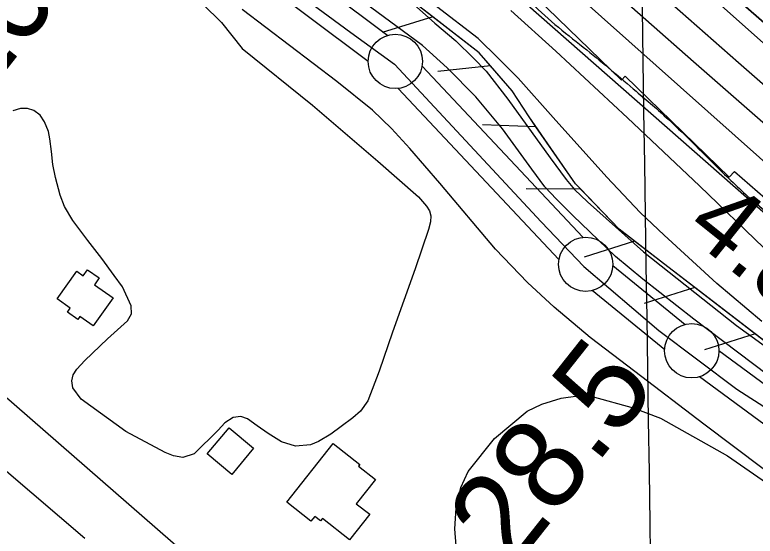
# Model space of a CAD drawing. Extents: x 3823584 to 3861785, y 301729 to 327625.
# Drawn here: x 3837614 to 3838296, y 323402 to 323882 of the extents above; entities that cross this region are included whole.
import ezdxf

# ---------------------------------------------------------------- set-up
doc = ezdxf.new("R2010")
doc.units = 0
for name, color, linetype in [('V-BLDG-OTLN', 7, 'Continuous'), ('V-FLOD-BASE', 7, 'Continuous'), ('V-GRID-MAJR', 7, 'Continuous'), ('V-LEVE-TOET', 7, 'Continuous'), ('V-RIVR-EDGE', 7, 'Continuous'), ('V-RIVR-RANG', 7, 'Continuous'), ('V-RIVR-RANG-IDEN', 7, 'Continuous'), ('V-ROAD-CNTR', 7, 'Continuous'), ('V-RRAP-FSHR', 7, 'Continuous'), ('V-RRAP-RVMT', 7, 'Continuous'), ('V-SITE-VEGE', 7, 'Continuous'), ('V-SURV-LINE', 7, 'Continuous'), ('V-TOPO-DPTH', 7, 'Continuous'), ('V-TOPO-MINR', 7, 'Continuous'), ('V-TOPO-WATR', 7, 'Continuous')]:
    doc.layers.add(name, color=color, linetype=linetype)

msp = doc.modelspace()

# ---------------------------------------------------------------- linework, layer by layer
at = {"layer": 'V-BLDG-OTLN'}
for points in [[(3837704.382, 323620.898), (3837686.186, 323595.218), (3837673.8850000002, 323603.934), (3837671.897, 323601.128), (3837662.404, 323607.856), (3837664.931, 323611.42100000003), (3837652.912, 323619.93700000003), (3837671.041, 323645.525), (3837676.992, 323641.306), (3837680.943, 323646.881), (3837691.6520000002, 323639.293), (3837687.23, 323633.05)], [(3837813.7290000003, 323458.43200000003), (3837791.094, 323477.337), (3837811.208, 323501.417), (3837833.84, 323482.512)], [(3837922.269, 323398.243), (3837897.261, 323417.955), (3837895.333, 323415.51), (3837890.082, 323419.647), (3837886.6520000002, 323415.295), (3837864.531, 323432.729), (3837907.109, 323486.749), (3837931.585, 323467.455), (3837930.487, 323466.063), (3837945.978, 323453.855), (3837928.308, 323431.43700000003), (3837940.721, 323421.654)]]:
    msp.add_lwpolyline(points, close=True, dxfattribs=at)
at = {"layer": 'V-FLOD-BASE'}
for points in [[(3837614.6040000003, 324124.417), (3837627.363, 324120.974), (3837647.0300000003, 324069.67), (3837741.944, 324004.683), (3837760.755, 323987.582), (3837818.9, 323947.392), (3837841.133, 323926.015), (3837923.219, 323865.306), (3837963.409, 323836.232), (3838098.511, 323690.87), (3838137.845, 323649.826), (3838207.1070000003, 323590.825), (3838278.932, 323536.956), (3838308.005, 323518.143)], [(3838540.65, 323375.59), (3838440.128, 323450.043), (3838334.771, 323529.086), (3838239.1950000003, 323601.329), (3838192.201, 323638.091), (3838167.136, 323659.156), (3838127.884, 323696.866), (3838112.796, 323711.925), (3838102.052, 323723.193), (3838089.949, 323739.526), (3838062.8910000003, 323776.568), (3838038.3680000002, 323806.162), (3838012.1410000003, 323832.689), (3837989.255, 323853.44800000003), (3837958.84, 323875.835), (3837915.983, 323907.51300000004), (3837868.285, 323941.999), (3837806.671, 323988.462), (3837738.9280000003, 324037.739), (3837671.686, 324088.401)]]:
    msp.add_lwpolyline(points, dxfattribs=at)
at = {"layer": 'V-GRID-MAJR'}
msp.add_spline([(3838444.8910000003, 307319.343), (3838352.38, 313376.366), (3838259.823, 319436.473), (3838167.2660000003, 325496.576), (3838167.219, 325499.664)], degree=3, dxfattribs=at)
at = {"layer": 'V-LEVE-TOET'}
for points in [[(3838383.812, 323402.648), (3838248.343, 323504.672), (3838184.759, 323553.031), (3838143.8850000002, 323584.601), (3838110.623, 323612.259), (3838086.062, 323635.01), (3838056.589, 323665.72000000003), (3838005.272, 323726.605), (3837977.788, 323758.396), (3837960.937, 323777.03500000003), (3837943.382, 323793.89400000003), (3837910.413, 323820.262), (3837823.328, 323886.607)], [(3837983.69, 323888.862), (3838000.66, 323873.989), (3838019.9050000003, 323857.616), (3838036.275, 323841.756), (3838047.907, 323829.591), (3838067.99, 323803.991), (3838106.949, 323750.02), (3838121.7090000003, 323729.806), (3838129.3910000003, 323720.738), (3838141.327, 323709.365), (3838192.728, 323663.256), (3838278.414, 323595.531), (3838359.394, 323536.76)]]:
    msp.add_lwpolyline(points, dxfattribs=at)
at = {"layer": 'V-RIVR-EDGE'}
msp.add_spline([(3836304.3756208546, 325474.18490968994), (3836346.414637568, 325438.3248399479), (3836389.407230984, 325406.0749957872), (3836417.6425015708, 325385.4333151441), (3836442.6682071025, 325366.7281829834), (3836470.247893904, 325340.94515767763), (3836497.8244014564, 325313.8763988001), (3836554.9028376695, 325258.4483785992), (3836598.5128638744, 325215.91107623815), (3836636.356164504, 325181.10248193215), (3836681.25510353, 325139.84773389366), (3836737.070060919, 325093.42302794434), (3836790.9421113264, 325041.2172897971), (3836840.3252216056, 324993.52274652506), (3836889.068644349, 324947.1155264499), (3836934.613629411, 324907.1449223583), (3836980.8110190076, 324871.0299293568), (3837015.471778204, 324849.0866188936), (3837040.494304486, 324829.09575316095), (3837085.3916538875, 324787.1981383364), (3837143.7621821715, 324734.3384060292), (3837181.60866205, 324700.815545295), (3837223.2932671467, 324659.5687453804), (3837272.052586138, 324619.5901931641), (3837314.3832372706, 324579.6275371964), (3837346.4455057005, 324546.7618498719), (3837364.398086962, 324527.4313367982), (3837395.83179523, 324500.35304017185), (3837442.024415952, 324462.30944681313), (3837492.7139249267, 324422.9689925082), (3837554.3051456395, 324372.67277922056), (3837573.562535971, 324361.05348832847), (3837583.2007688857, 324359.1010435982), (3837596.685075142, 324352.6389936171), (3837621.0774516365, 324337.7926517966), (3837648.0333471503, 324319.7256175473), (3837677.5368654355, 324292.00922300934), (3837718.5754244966, 324249.4782791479), (3837753.847257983, 324214.6760433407), (3837781.426944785, 324188.89301803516), (3837800.047826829, 324179.8467839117), (3837819.9544424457, 324170.79737053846), (3837850.7214395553, 324134.0776617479), (3837874.448694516, 324110.2327745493), (3837909.0728923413, 324073.5035280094), (3837941.7780275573, 324040.63625106), (3837989.872225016, 323991.65915346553), (3838022.5821291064, 323960.7204768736), (3838034.1219387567, 323947.83452790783), (3838046.301435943, 323933.66125574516), (3838066.8302532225, 323916.25298453), (3838089.9146413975, 323892.40968695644), (3838140.5946126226, 323849.2120319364), (3838186.144366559, 323811.1700282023), (3838215.652653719, 323785.38223402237), (3838265.675451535, 323736.40036755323), (3838297.1043909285, 323707.3934705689), (3838336.8747022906, 323671.9372406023), (3838359.952731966, 323645.5224758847), (3838385.6228939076, 323627.4586208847), (3838404.2374174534, 323615.8409196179), (3838421.5598489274, 323601.65493045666), (3838441.441030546, 323582.31964850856), (3838460.0476059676, 323567.48761331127), (3838468.395336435, 323563.60974747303), (3838484.446340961, 323555.21273863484), (3838548.5883636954, 323496.55289863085), (3838595.4381578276, 323464.2935167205), (3838649.9785090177, 323422.37205752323), (3838701.302936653, 323379.8156796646), (3838749.433695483, 323345.62451814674), (3838798.2232173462, 323317.86043486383), (3838856.617590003, 323274.6437043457), (3838932.9883882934, 323221.7394625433), (3838989.4684672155, 323184.31330197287), (3839037.599226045, 323150.12214045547), (3839068.4186807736, 323134.6170356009), (3839093.417362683, 323104.98316807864), (3839110.730256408, 323086.93997820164), (3839122.930418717, 323081.1239742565), (3839143.464004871, 323065.6443033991), (3839172.3405526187, 323044.35816634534), (3839190.955076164, 323032.7404650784), (3839215.98555057, 323015.9639332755), (3839242.319244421, 323006.25575686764), (3839316.801182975, 322969.42795358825), (3839341.8396055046, 322955.86575571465), (3839371.3828644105, 322944.2210308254), (3839391.2910696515, 322935.81448423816), (3839417.6104568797, 322920.32050675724), (3839461.26181333, 322894.4977408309), (3839483.709693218, 322873.22750002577), (3839520.2990527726, 322851.27942068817), (3839555.6010891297, 322828.6916538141), (3839599.9048501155, 322806.7244989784), (3839718.698497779, 322751.1438747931), (3839768.138834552, 322726.5925358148), (3839807.9457072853, 322705.9222419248), (3839836.8508682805, 322696.20770701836), (3839865.0988558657, 322680.7089606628), (3839887.567400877, 322667.7959880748), (3839924.172656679, 322652.2765765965), (3839969.7621512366, 322630.306242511), (3840004.4324481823, 322612.2201327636), (3840037.8249596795, 322597.35153619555), (3840085.3541819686, 322579.87650073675), (3840108.4624145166, 322565.6762049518), (3840121.9212867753, 322548.928286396), (3840123.184765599, 322539.92497214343), (3840122.5260025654, 322533.4978939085), (3840117.9957321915, 322521.29455234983), (3840112.8353120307, 322514.2357347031), (3840095.465191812, 322509.1357202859), (3840089.6793907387, 322509.1500269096), (3840085.168195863, 322504.661086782), (3840084.5094328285, 322498.2340085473), (3840085.779270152, 322491.8021614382), (3840130.719539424, 322467.2619498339), (3840169.888314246, 322448.52184592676), (3840197.5093312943, 322439.45335705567), (3840209.076164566, 322437.4961434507), (3840231.586039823, 322441.2977072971), (3840246.3910513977, 322448.9755473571), (3840266.343766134, 322458.5692707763), (3840273.434376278, 322466.26618633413), (3840278.590027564, 322471.3964036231), (3840288.898150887, 322480.37110462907), (3840295.9808129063, 322484.8536862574), (3840301.7666139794, 322484.8393796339), (3840308.195281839, 322484.8234833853), (3840320.395444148, 322479.00747944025), (3840324.873256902, 322469.99621706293), (3840326.781192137, 322461.6341799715), (3840338.324181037, 322450.0339645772), (3840344.7401318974, 322444.87513404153), (3840366.580116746, 322437.7495521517), (3840385.842275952, 322428.05886161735), (3840421.7967168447, 322409.3267058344), (3840466.0957089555, 322385.43095064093), (3840492.411916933, 322368.65123958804), (3840506.526372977, 322357.0446656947), (3840533.4854477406, 322340.2633650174), (3840559.1778644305, 322331.1996450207), (3840587.441748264, 322322.12956652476), (3840611.8452521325, 322311.78329220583), (3840642.0218400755, 322296.27977697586), (3840678.615968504, 322276.2602979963), (3840712.637040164, 322255.60431073), (3840733.1753951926, 322242.05324023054), (3840784.5268464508, 322210.42559773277), (3840835.889425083, 322183.29802273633), (3840892.388579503, 322153.5862635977), (3840923.854080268, 322139.3653026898), (3840950.8242824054, 322127.08406951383), (3840989.3295253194, 322099.98828701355), (3841017.5727440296, 322082.56094030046), (3841061.238407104, 322062.5239754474), (3841092.6943701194, 322044.4458138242), (3841151.0982805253, 322005.0862840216), (3841210.7847452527, 321964.43784139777), (3841240.294622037, 321939.29291400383), (3841299.971549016, 321894.78727066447), (3841335.8926077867, 321862.55491237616), (3841374.3692374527, 321823.88752772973), (3841411.5712609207, 321789.72338983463), (3841444.922442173, 321758.1402568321), (3841469.94019958, 321736.22079074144), (3841482.124465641, 321723.9761189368), (3841496.2198461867, 321704.6551436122), (3841509.051747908, 321694.3374825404), (3841523.1773313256, 321687.23097614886), (3841573.8986327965, 321660.747857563), (3841623.970708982, 321631.69486145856), (3841667.623655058, 321606.5149623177), (3841696.5208679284, 321593.58609348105), (3841738.2626995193, 321575.48249786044), (3841787.074476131, 321556.7185495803), (3841815.992354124, 321552.1469489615), (3841851.3325414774, 321544.9879849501), (3841886.661601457, 321533.32895343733), (3841930.322495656, 321511.36338822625), (3841950.219573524, 321498.4567741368), (3841977.1818275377, 321482.9612070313), (3841998.380535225, 321476.4800815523), (3842052.9924195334, 321463.4876277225), (3842082.546805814, 321456.3429703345), (3842109.5185975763, 321444.7046039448), (3842146.1190845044, 321427.2565921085), (3842196.2006984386, 321402.06079671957), (3842241.1346092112, 321374.94911797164), (3842288.6336286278, 321345.2596135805), (3842321.375325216, 321327.17827270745), (3842366.940975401, 321295.56493683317), (3842395.188962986, 321280.06619047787), (3842429.2227516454, 321264.5531374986), (3842452.3516493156, 321258.7101099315), (3842470.9725313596, 321249.663875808)], degree=3, dxfattribs=at)
at = {"layer": 'V-ROAD-CNTR'}
msp.add_lwpolyline([(3835362.231236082, 325460.9250527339), (3835509.512941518, 325334.346305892), (3835871.754217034, 325022.76592905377), (3836108.39574375, 324817.59833938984), (3836413.993132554, 324556.9258607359), (3836839.7512810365, 324193.6555872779), (3837163.6936331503, 323918.79213700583), (3837445.019070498, 323669.35663587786), (3837836.483287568, 323328.41131777), (3838069.5748213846, 323134.8777048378), (3838125.3817097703, 323086.7958010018), (3838255.977448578, 322989.4639956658), (3838600.004760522, 322735.3525038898), (3839019.3109219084, 322425.41512376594), (3839565.53882945, 322022.9139287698), (3840024.8789107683, 321675.2296241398), (3840474.8730107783, 321349.99327461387), (3840728.35650381, 321161.30865198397)], dxfattribs=at)
at = {"layer": 'V-RRAP-FSHR'}
for p, q in [((3837998.901, 323879.704), (3837952.2320000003, 323865.338)), ((3838052.042, 323834.491), (3838003.489, 323829.29)), ((3838093.46, 323778.288), (3838044.667, 323780.19800000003)), ((3838133.739, 323721.028), (3838084.9080000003, 323721.19800000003)), ((3838184.6920000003, 323673.09500000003), (3838138.129, 323658.386)), ((3838240.214, 323630.468), (3838193.629, 323615.83)), ((3838295.7060000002, 323587.8), (3838249.1210000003, 323573.162))]:
    msp.add_line(p, q, dxfattribs=at)
for points in [[(3836295.022645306, 325470.7968986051), (3836414.504487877, 325364.55863442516), (3836757.995048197, 325057.7969061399), (3837184.2616725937, 324676.31799378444), (3837417.6558488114, 324483.21002560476), (3837615.799848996, 324305.9576734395), (3837777.405481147, 324176.4257693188), (3837917.933097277, 324038.7141531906), (3838584.546857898, 323453.1786646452)], [(3838516.713, 323417.868), (3838211.373, 323652.64400000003), (3838170.335, 323684.099), (3838130.324, 323725.941), (3838087.472, 323787.59500000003), (3838072.042, 323811.577), (3838041.543, 323846.521), (3837978.9390000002, 323895.239), (3837748.075, 324066.564), (3837693.8540000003, 324106.458), (3837694.89, 324135.743), (3837697.0100000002, 324164.456), (3837695.298, 324176.805), (3837684.201, 324193.14400000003), (3837666.4820000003, 324209.091), (3837608.497, 324250.814), (3837483.473, 324345.729), (3837295.8910000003, 324482.542), (3837082.919, 324641.37), (3836929.9, 324758.229), (3836898.7800000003, 324781.855)], [(3837998.901, 323879.704), (3837978.9390000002, 323895.239), (3837943.039, 323921.88)], [(3838052.042, 323834.491), (3838041.543, 323846.521), (3837998.901, 323879.705)], [(3838093.788, 323778.507), (3838087.472, 323787.59500000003), (3838072.042, 323811.577), (3838052.042, 323834.492)], [(3838134.4590000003, 323721.617), (3838130.324, 323725.941), (3838093.788, 323778.50800000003)], [(3838184.6920000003, 323673.09500000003), (3838170.335, 323684.099), (3838134.458, 323721.618)], [(3838295.7060000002, 323587.8), (3838240.214, 323630.468), (3838211.373, 323652.64400000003), (3838184.691, 323673.09500000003)], [(3838351.198, 323545.13300000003), (3838295.705, 323587.801)]]:
    msp.add_lwpolyline(points, dxfattribs=at)
at = {"layer": 'V-RRAP-RVMT'}
for p, q in [((3838082.037000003, 323909.61800000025), (3838172.7520000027, 323821.48400000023)), ((3838172.7520000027, 323821.48400000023), (3838176.1280000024, 323825.0290000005)), ((3838176.128000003, 323825.0290000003), (3838271.7100000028, 323732.11700000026)), ((3838271.7100000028, 323732.11700000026), (3838276.6870000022, 323737.31000000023)), ((3838276.6870000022, 323737.31000000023), (3838377.613000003, 323648.953))]:
    msp.add_line(p, q, dxfattribs=at)
at = {"layer": 'V-SITE-VEGE'}
for points in [[(3838301.954, 323599.185), (3838260.5, 323634.13), (3838211.87, 323678.731), (3838189.778, 323699.684), (3838159.1240000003, 323732.09), (3838109.657, 323786.913), (3838077.437, 323823.093), (3838059.098, 323841.641), (3838040.559, 323859.69800000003), (3838002.352, 323889.37), (3837949.224, 323928.24700000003), (3837926.424, 323947.22000000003), (3837914.802, 323960.673), (3837909.188, 323967.647), (3837898.545, 323979.212), (3837886.603, 323989.097), (3837874.853, 323998.188), (3837862.309, 324006.987), (3837849.686, 324018.957), (3837842.792, 324027.229), (3837823.469, 324047.072), (3837811.2260000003, 324056.266)], [(3837769.846, 323908.697), (3837804.353, 323874.592), (3837823.35, 323850.489)], [(3838070.6550000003, 323885.507), (3838112.09, 323848.183), (3838177.98, 323786.72000000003), (3838244.556, 323724.064), (3838303.631, 323667.002)], [(3837823.35, 323850.489), (3837888.194, 323798.45900000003), (3837948.082, 323746.759), (3837985.769, 323714.12), (3837993.056, 323705.255), (3837995.808, 323701.075), (3837997.0700000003, 323696.407), (3837996.642, 323690.958), (3837994.8170000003, 323683.829), (3837982.5130000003, 323647.71), (3837961.855, 323589.43), (3837949.454, 323553.412), (3837939.085, 323526.204), (3837932.29, 323516.724), (3837925.312, 323510.619), (3837914.46, 323502.449), (3837904.8030000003, 323495.466), (3837893.558, 323488.689), (3837886.203, 323485.558), (3837872.318, 323484.349), (3837859.649, 323488.48600000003), (3837847.199, 323496.092), (3837837.2260000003, 323502.992), (3837828.241, 323509.587), (3837822.105, 323511.803), (3837814.861, 323510.656), (3837807.3000000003, 323506.038), (3837801.113, 323499.03500000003), (3837779.177, 323477.347), (3837768.747, 323474.03500000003), (3837760.028, 323475.375), (3837752.412, 323478.492), (3837716.1350000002, 323497.835), (3837675.061, 323527.615), (3837667.389, 323538.26900000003), (3837666.531, 323544.51900000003), (3837667.754, 323550.065), (3837670.955, 323555.204), (3837678.239, 323563.291), (3837699.373, 323583.298), (3837717.7120000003, 323599.949), (3837721.319, 323606.373), (3837721.159, 323613.512), (3837713.129, 323631.009), (3837705.259, 323641.564), (3837693.9450000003, 323657.096), (3837681.1520000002, 323673.627), (3837667.475, 323692.147), (3837659.815, 323705.181), (3837655.613, 323715.515), (3837651.245, 323731.89900000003), (3837648.932, 323743.81), (3837647.613, 323755.715), (3837646.094, 323767.426), (3837644.845, 323774.272), (3837641.2260000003, 323782.92100000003), (3837637.294, 323789.09), (3837631.469, 323793.485), (3837625.5300000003, 323795.205), (3837619.185, 323795.24), (3837611.935, 323793.102)], [(3837181.573, 323388.368), (3837235.806, 323443.369), (3837288.271, 323500.754), (3837323.0100000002, 323543.571), (3837334.6010000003, 323560.06), (3837339.41, 323568.755), (3837343.438, 323580.03), (3837344.782, 323589.438), (3837343.852, 323600.248), (3837338.026, 323621.393), (3837336.223, 323635.477), (3837337.473, 323645.783), (3837342.39, 323656.357), (3837348.065, 323660.983), (3837352.433, 323662.146), (3837356.988, 323661.427), (3837361.4420000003, 323660.215), (3837388.785, 323640.53), (3837439.117, 323602.38), (3837516.558, 323538.201), (3837606.316, 323461.369), (3837678.3170000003, 323399.703)], [(3838022.166, 323369.272), (3838019.018, 323408.256), (3838020.3170000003, 323427.284), (3838024.6890000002, 323446.396), (3838031.417, 323461.031), (3838055.684, 323491.53), (3838085.771, 323516.63800000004), (3838099.191, 323523.106), (3838117.169, 323528.457), (3838132.252, 323530.65), (3838145.632, 323530.079), (3838183.251, 323519.651), (3838208.481, 323510.185), (3838270.248, 323475.526), (3838321.997, 323439.637)]]:
    msp.add_lwpolyline(points, dxfattribs=at)
at = {"layer": 'V-SURV-LINE'}
for points in [[(3837677.831647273, 324072.2282276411), (3837957.3420831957, 323862.61222554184)], [(3837939.325520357, 323838.62464664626), (3837659.815136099, 324048.2406100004)], [(3837988.948749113, 323834.3080306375), (3838136.858693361, 323676.7065996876)], [(3838114.9687699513, 323656.1924162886), (3837967.058757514, 323813.7939198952)], [(3838164.54895194, 323650.8873931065), (3838231.325604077, 323596.4712464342)], [(3838212.381452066, 323573.2092776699), (3838145.605106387, 323627.62517461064)], [(3838262.3282462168, 323572.4525766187), (3838967.899995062, 323053.09216806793)], [(3838950.103352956, 323028.9409823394), (3838244.5316223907, 323548.30137743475)]]:
    msp.add_lwpolyline(points, dxfattribs=at)
for centre in [(3837964.3254700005, 323838.6258), (3838139.59206, 323651.87473000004), (3838237.338330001, 323572.2216199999)]:
    msp.add_circle(centre, 25, dxfattribs=at)
at = {"layer": 'V-TOPO-DPTH'}
for points in [[(3838382.7371031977, 323805.5230493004), (3837860.9331754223, 324260.5584050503), (3837832.560879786, 324285.4311535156), (3837804.275892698, 324310.4022774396), (3837776.121868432, 324335.5209645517), (3837748.0551527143, 324360.7380271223), (3837699.881196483, 324404.2489813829), (3837695.951561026, 324407.76680775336), (3837692.0014180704, 324411.2612445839), (3837688.0205138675, 324414.7205971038), (3837684.0191021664, 324418.1565600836), (3837578.9735416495, 324507.55360117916), (3837522.3488812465, 324555.5693497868), (3837465.6107774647, 324603.45018290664), (3837408.7025086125, 324651.1286427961), (3837351.6807963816, 324698.6721871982), (3836968.178114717, 325017.27296973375)], [(3838382.7371031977, 323805.5230493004), (3837860.9331754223, 324260.5584050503), (3837832.560879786, 324285.4311535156), (3837804.275892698, 324310.4022774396), (3837776.121868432, 324335.5209645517), (3837748.0551527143, 324360.7380271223), (3837699.881196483, 324404.2489813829), (3837695.951561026, 324407.76680775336), (3837692.0014180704, 324411.2612445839), (3837688.0205138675, 324414.7205971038), (3837684.0191021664, 324418.1565600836), (3837578.9735416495, 324507.55360117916), (3837522.3488812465, 324555.5693497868), (3837465.6107774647, 324603.45018290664), (3837408.7025086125, 324651.1286427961), (3837351.6807963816, 324698.6721871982), (3836968.178114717, 325017.27296973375)], [(3836971.9178616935, 324972.83050933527), (3837252.283767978, 324737.8850834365), (3837322.0034214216, 324679.353446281), (3837391.652678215, 324620.7383131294), (3837461.196340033, 324561.99793598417), (3837530.6696052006, 324503.1740628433), (3837611.3959127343, 324434.6972930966), (3837640.340531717, 324409.9202919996), (3837669.1349194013, 324384.971469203), (3837697.7039601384, 324359.76491385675), (3837726.122769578, 324334.38653681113), (3838066.8243204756, 324027.3728192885), (3838119.971225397, 323979.69030236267), (3838173.255810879, 323932.1628219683), (3838226.746917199, 323884.8678963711), (3838280.3757040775, 323837.7280073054), (3838339.2406858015, 323786.21231701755)], [(3836971.9178616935, 324972.83050933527), (3837252.283767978, 324737.8850834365), (3837322.0034214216, 324679.353446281), (3837391.652678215, 324620.7383131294), (3837461.196340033, 324561.99793598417), (3837530.6696052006, 324503.1740628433), (3837611.3959127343, 324434.6972930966), (3837640.340531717, 324409.9202919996), (3837669.1349194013, 324384.971469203), (3837697.7039601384, 324359.76491385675), (3837726.122769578, 324334.38653681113), (3838066.8243204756, 324027.3728192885), (3838119.971225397, 323979.69030236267), (3838173.255810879, 323932.1628219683), (3838226.746917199, 323884.8678963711), (3838280.3757040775, 323837.7280073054), (3838339.2406858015, 323786.21231701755)], [(3838324.934771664, 323727.84568335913), (3838008.706183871, 324009.45784384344), (3837946.1737909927, 324065.22076796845), (3837883.691674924, 324121.0398939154), (3837821.284974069, 324176.94332259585), (3837758.928550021, 324232.9029530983), (3837651.055469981, 324329.84148260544), (3837642.64045044, 324337.3363473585), (3837634.181647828, 324344.78101785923), (3837625.657170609, 324352.1503969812), (3837617.0889103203, 324359.46958185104), (3837330.422620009, 324602.1558655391), (3837256.6802777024, 324663.8755040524), (3837182.482062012, 324725.03570046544), (3837107.600036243, 324785.35673372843), (3837032.2621370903, 324845.1183248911)]]:
    msp.add_lwpolyline(points, dxfattribs=at)
at = {"layer": 'V-TOPO-MINR'}
for points in [[(3836968.178114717, 325017.27296973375), (3837351.6807963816, 324698.6721871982), (3837408.7025086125, 324651.1286427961), (3837465.6107774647, 324603.45018290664), (3837522.3488812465, 324555.5693497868), (3837578.9735416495, 324507.55360117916), (3837684.0191021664, 324418.1565600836), (3837688.0205138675, 324414.7205971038), (3837692.0014180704, 324411.2612445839), (3837695.951561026, 324407.76680775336), (3837699.881196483, 324404.2489813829), (3837748.0551527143, 324360.7380271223), (3837776.121868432, 324335.5209645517), (3837804.275892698, 324310.4022774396), (3837832.560879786, 324285.4311535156), (3837860.9331754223, 324260.5584050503), (3838382.7371031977, 323805.5230493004)], [(3836970.0586820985, 324997.1175565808), (3837628.9950841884, 324452.9762194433), (3837638.6086303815, 324445.0056336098), (3837648.201167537, 324437.00994346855), (3837657.7621911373, 324428.97659686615), (3837667.3022057, 324420.91814595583), (3837684.932040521, 324405.96673235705), (3837685.638491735, 324405.3618598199), (3837687.7308906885, 324403.5164530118), (3837696.1927654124, 324395.8702342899), (3837701.1188868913, 324391.4292447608), (3837706.0518067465, 324386.9958371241), (3837710.9949241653, 324382.57380232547), (3837715.944839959, 324378.15934941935), (3838361.295295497, 323803.9532928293)], [(3836971.9178616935, 324972.83050933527), (3837252.283767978, 324737.8850834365), (3837322.0034214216, 324679.353446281), (3837391.652678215, 324620.7383131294), (3837461.196340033, 324561.99793598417), (3837530.6696052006, 324503.1740628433), (3837611.3959127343, 324434.6972930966), (3837640.340531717, 324409.9202919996), (3837669.1349194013, 324384.971469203), (3837697.7039601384, 324359.76491385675), (3837726.122769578, 324334.38653681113), (3838066.8243204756, 324027.3728192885), (3838119.971225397, 323979.69030236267), (3838173.255810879, 323932.1628219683), (3838226.746917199, 323884.8678963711), (3838280.3757040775, 323837.7280073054), (3838339.2406858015, 323786.21231701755)], [(3837123.035889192, 324815.42369030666), (3837165.697822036, 324778.91920664), (3837614.615881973, 324394.3863041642), (3837632.534403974, 324378.9380260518), (3837650.386447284, 324363.4137931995), (3837668.1387725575, 324347.775628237), (3837685.824619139, 324332.06150853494), (3838107.247108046, 323955.20173551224), (3838151.018769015, 323916.2039689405), (3838194.8860438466, 323877.3144568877), (3838238.896739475, 323838.58732661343), (3838283.0030489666, 323799.96845085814), (3838362.0912485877, 323730.97767757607)]]:
    msp.add_lwpolyline(points, dxfattribs=at)
at = {"layer": 'V-TOPO-WATR'}
msp.add_lwpolyline([(3837032.2621370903, 324845.1183248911), (3837107.600036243, 324785.35673372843), (3837182.482062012, 324725.03570046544), (3837256.6802777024, 324663.8755040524), (3837330.422620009, 324602.1558655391), (3837617.0889103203, 324359.46958185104), (3837625.657170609, 324352.1503969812), (3837634.181647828, 324344.78101785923), (3837642.64045044, 324337.3363473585), (3837651.055469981, 324329.84148260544), (3837758.928550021, 324232.9029530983), (3837821.284974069, 324176.94332259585), (3837883.691674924, 324121.0398939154), (3837946.1737909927, 324065.22076796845), (3838008.706183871, 324009.45784384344), (3838324.934771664, 323727.84568335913)], dxfattribs=at)

# ---------------------------------------------------------------- texts
at = {"layer": 'V-RIVR-RANG'}
msp.add_text('4.8', height=66.99999999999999, rotation=321.4483257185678, dxfattribs=at).set_placement((3838229.15786607, 323681.23069065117))
at = {"layer": 'V-RIVR-RANG-IDEN'}
for s, height, rotation, p in [('D-100', 83, 51.84932571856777, (3837508.9014954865, 323706.8790460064)), ('R-28.5', 82.99999799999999, 51.59333483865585, (3837999.360762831, 323277.77959259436))]:
    msp.add_text(s, height=height, rotation=rotation, dxfattribs=at).set_placement(p)

doc.saveas('drawing.dxf')
